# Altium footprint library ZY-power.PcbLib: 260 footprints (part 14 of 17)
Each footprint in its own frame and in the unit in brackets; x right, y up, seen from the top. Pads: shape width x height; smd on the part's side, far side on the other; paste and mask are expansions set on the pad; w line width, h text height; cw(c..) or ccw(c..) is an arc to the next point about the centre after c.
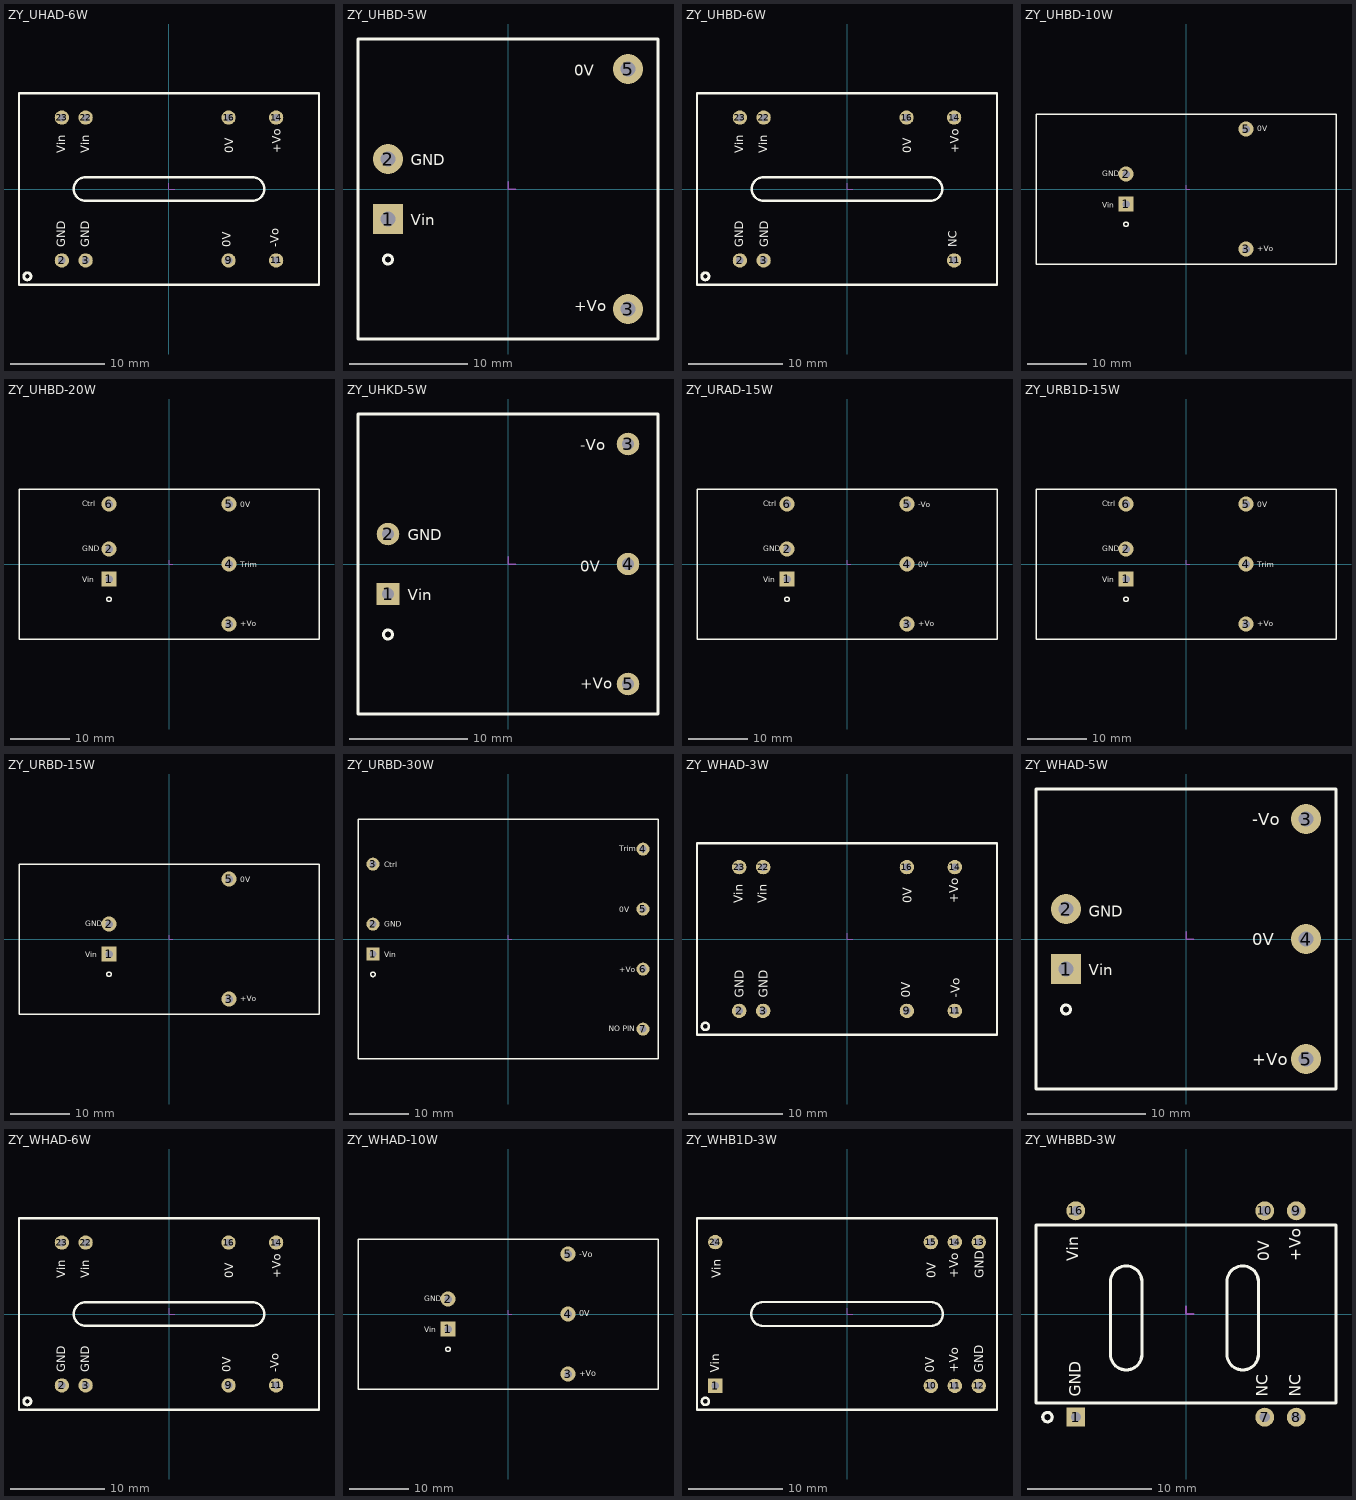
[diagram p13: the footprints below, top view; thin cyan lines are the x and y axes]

## ZY_UHAD-6W [mil]
height 413.39
pads (8):
  round 60 hole 32: 2(-450,-300) 3(-350,-300) 9(250,-300) 11(450,-300) 14(450,300) 16(250,300) 22(-350,300) 23(-450,300)
Top Overlay:
  circle w12: c-594.92,-366.57 r15
  lines w10: -629.92,-401.57 -629.92,401.57 629.92,401.57 629.92,-401.57 -629.92,-401.57 ; -400,0 ccw(c-350,0) -350,-50 350,-50 ccw(c350,0) 400,0 ccw(c350,0) 350,50 -350,50 ccw(c-350,0) -400,0
  text "0V" at 260,-245 h36
  text "GND" at -435,-245 h36
  text "GND" at -335,-245 h36
  text "Vin" at -435,150 h36
  text "Vin" at -335,150 h36
  text "-Vo" at 460,-245 h36
  text "+Vo" at 470,150 h36
  text "0V" at 270,150 h36
Mechanical 15:
  lines w5: 0,25 0,0 25,0

## ZY_UHBD-5W [mil]
height 460.63
pads (4):
  rect 100x100 hole 50: 1(-400,-100)
  round 100 hole 50: 2(-400,100) 3(400,-400) 5(400,400)
Top Overlay:
  circle w10: c-400,-235 r15
  lines w10: -500,-500 -500,500 500,500 500,-500 -500,-500
  text "GND" at -325,80 h36
  text "Vin" at -325,-120 h36
  text "+Vo" at 220,-408 h36
  text "0V" at 220,377 h36
Mechanical 15:
  lines w5: 0,25 0,0 25,0

## ZY_UHBD-6W [mil]
height 413.39
pads (7):
  round 60 hole 32: 2(-450,-300) 3(-350,-300) 11(450,-300) 14(450,300) 16(250,300) 22(-350,300) 23(-450,300)
Top Overlay:
  circle w12: c-594.92,-366.57 r15
  lines w10: -629.92,-401.57 -629.92,401.57 629.92,401.57 629.92,-401.57 -629.92,-401.57 ; -400,0 ccw(c-350,0) -350,-50 350,-50 ccw(c350,0) 400,0 ccw(c350,0) 350,50 -350,50 ccw(c-350,0) -400,0
  text "GND" at -435,-245 h36
  text "GND" at -330,-245 h36
  text "Vin" at -435,150 h36
  text "Vin" at -335,150 h36
  text "NC" at 460,-245 h36
  text "+Vo" at 470,150 h36
  text "0V" at 270,150 h36
Mechanical 15:
  lines w5: 0,25 0,0 25,0

## ZY_UHBD-10W [mil]
height 500
pads (4):
  rect 100x100 hole 50: 1(-400,-100)
  round 100 hole 50: 2(-400,100) 3(400,-400) 5(400,400)
Top Overlay:
  circle w10: c-400,-235 r15
  lines w10: -1000,-500 1000,-500 1000,500 -1000,500 -1000,-500
  text "0V" at 475,385 h36
  text "+Vo" at 475,-415 h36
  text "GND" at -560,85 h36
  text "Vin" at -560,-125 h36
Mechanical 15:
  lines w5: 0,25 0,0 25,0

## ZY_UHBD-20W [mil]
pads (6):
  rect 100x100 hole 50: 1(-400,-100)
  round 100 hole 50: 2(-400,100) 3(400,-400) 4(400,0) 5(400,400) 6(-400,400)
Top Overlay:
  circle w10: c-400,-235 r15
  lines w10: -1000,-500 -1000,500 1000,500 1000,-500 -1000,-500
  text "+Vo" at 475,-415 h36
  text "0V" at 475,380 h36
  text "GND" at -580,85 h36
  text "Vin" at -580,-120 h36
  text "Trim" at 475,-20 h36
  text "Ctrl" at -580,385 h36
Mechanical 15:
  lines w5: 0,25 0,0 25,0

## ZY_UHKD-5W [mil]
pads (5):
  rect 75x75 hole 40: 1(-400,-100)
  round 75 hole 40: 2(-400,100) 3(400,400) 4(400,0) 5(400,-400)
Top Overlay:
  circle w10: c-400,-235 r15
  lines w10: -500,-500 500,-500 500,500 -500,500 -500,-500
  text "+Vo" at 240,-415 h36
  text "-Vo" at 240,380 h36
  text "0V" at 240,-25 h36
  text "GND" at -335,80 h36
  text "Vin" at -335,-120 h36
Mechanical 15:
  lines w5: 0,25 0,0 25,0

## ZY_URAD-15W [mil]
pads (6):
  rect 100x100 hole 50: 1(-400,-100)
  round 100 hole 50: 2(-400,100) 3(400,-400) 4(400,0) 5(400,400) 6(-400,400)
Top Overlay:
  circle w10: c-400,-235 r15
  lines w10: -1000,-500 -1000,500 1000,500 1000,-500 -1000,-500
  text "+Vo" at 475,-415 h36
  text "-Vo" at 475,380 h36
  text "GND" at -560,85 h36
  text "Vin" at -560,-120 h36
  text "0V" at 475,-20 h36
  text "Ctrl" at -560,385 h36
Mechanical 15:
  lines w5: 0,25 0,0 25,0

## ZY_URB1D-15W [mil]
pads (6):
  rect 100x100 hole 50: 1(-400,-100)
  round 100 hole 50: 2(-400,100) 3(400,-400) 4(400,0) 5(400,400) 6(-400,400)
Top Overlay:
  circle w10: c-400,-235 r15
  lines w10: -1000,-500 1000,-500 1000,500 -1000,500 -1000,-500
  text "Ctrl" at -560,385 h36
  text "Trim" at 475,-20 h36
  text "Vin" at -560,-120 h36
  text "GND" at -560,85 h36
  text "0V" at 475,380 h36
  text "+Vo" at 475,-415 h36
Mechanical 15:
  lines w5: 0,25 0,0 25,0

## ZY_URBD-15W [mil]
pads (4):
  rect 100x100 hole 50: 1(-400,-100)
  round 100 hole 50: 2(-400,100) 3(400,-400) 5(400,400)
Top Overlay:
  circle w10: c-400,-235 r15
  lines w10: -1000,-500 1000,-500 1000,500 -1000,500 -1000,-500
  text "Vin" at -560,-120 h36
  text "GND" at -560,85 h36
  text "0V" at 475,380 h36
  text "+Vo" at 475,-415 h36
Mechanical 15:
  lines w5: 0,25 0,0 25,0

## ZY_URBD-30W [mil]
height 492.13
pads (7):
  rect 87x87 hole 47: 1(-900,-100)
  round 87 hole 47: 2(-900,100) 3(-900,500) 4(900,600) 5(900,200) 6(900,-200) 7(900,-600)
Top Overlay:
  circle w10: c-900,-235 r15
  lines w10: -1000,-798.43 1000,-798.43 1000,800 -1000,800 -1000,-798.43
  text "Vin" at -825,-119.21 h36
  text "+Vo" at 740,-219.21 h36
  text "0V" at 740,180.79 h36
  text "Ctrl" at -825,480.79 h36
  text "Trim" at 740,585.79 h36
  text "GND" at -825,80.79 h36
  text "NO PIN" at 670,-615 h36
Mechanical 15:
  lines w5: 0,25 0,0 25,0

## ZY_WHAD-3W [mil] "宽压输入隔离稳压双输出电源模块"
height 374.02
pads (8):
  round 60 hole 32: 2(-450,-300) 3(-350,-300) 9(250,-300) 11(450,-300) 14(450,300) 16(250,300) 22(-350,300) 23(-450,300)
Top Overlay:
  circle w10: c-590.98,-364.61 r15
  lines w10: -625.98,-399.61 -551.38,-399.61 -550,-399.61 625.98,-399.61 625.98,399.61 -625.98,399.61 -625.98,-399.61
  text "GND" at -430,-245 h36
  text "GND" at -330,-245 h36
  text "0V" at 265,-245 h36
  text "-Vo" at 470,-245 h36
  text "+Vo" at 465,150 h36
  text "0V" at 270,150 h36
  text "Vin" at -335,150 h36
  text "Vin" at -435,150 h36
Mechanical 15:
  lines w5: 0,25 0,0 25,0

## ZY_WHAD-5W [mil]
height 460.63
pads (5):
  rect 100x100 hole 50: 1(-400,-100)
  round 100 hole 50: 2(-400,100) 3(400,400) 4(400,0) 5(400,-400)
Top Overlay:
  circle w10: c-400,-235 r15
  lines w10: -500,-500 500,-500 500,500 -500,500 -500,-500
  text "-Vo" at 220,380 h40
  text "+Vo" at 220,-420 h40
  text "Vin" at -325,-120 h36
  text "GND" at -325,75 h36
  text "0V" at 220,-20 h40
Mechanical 15:
  lines w5: 0,25 0,0 25,0

## ZY_WHAD-6W [mil]
height 413.39
pads (8):
  round 60 hole 32: 2(-450,-300) 3(-350,-300) 9(250,-300) 11(450,-300) 14(450,300) 16(250,300) 22(-350,300) 23(-450,300)
Top Overlay:
  circle w12: c-594.92,-366.57 r15
  lines w10: -629.92,-401.57 629.92,-401.57 629.92,401.57 -629.92,401.57 -629.92,-401.57 ; -400,0 cw(c-350,0) -350,50 350,50 cw(c350,0) 400,0 cw(c350,0) 350,-50 -350,-50 cw(c-350,0) -400,0
  text "0V" at 270,150 h36
  text "+Vo" at 470,150 h36
  text "-Vo" at 460,-245 h36
  text "Vin" at -335,150 h36
  text "Vin" at -435,150 h36
  text "GND" at -335,-245 h36
  text "GND" at -435,-245 h36
  text "0V" at 260,-245 h36
Mechanical 15:
  lines w5: 0,25 0,0 25,0

## ZY_WHAD-10W [mil]
pads (5):
  rect 100x100 hole 50: 1(-400,-100)
  round 100 hole 50: 2(-400,100) 3(400,-400) 4(400,0) 5(400,400)
Top Overlay:
  circle w10: c-400,-235 r15
  lines w10: -1000,-500 1000,-500 1000,500 -1000,500 -1000,-500
  text "Vin" at -560,-120 h36
  text "GND" at -560,85 h36
  text "0V" at 475,-15 h40
  text "+Vo" at 475,-415 h40
  text "-Vo" at 475,380 h40
Mechanical 15:
  lines w5: 0,25 0,0 25,0

## ZY_WHB1D-3W [mil]
height 413.39
pads (8):
  rect 60x60 hole 32: 1(-550,-300)
  round 60 hole 32: 10(350,-300) 11(450,-300) 12(550,-300) 13(550,300) 14(450,300) 15(350,300) 24(-550,300)
Top Overlay:
  circle w10: c-590.98,-364.61 r15
  lines w10: -550,-399.61 -551.38,-399.61 ; -551.38,-399.61 625.98,-399.61 625.98,399.61 -625.98,399.61 -625.98,-399.61 -551.38,-399.61 ; -400,0 ccw(c-350,0) -350,-50 350,-50 ccw(c350,0) 400,0 ccw(c350,0) 350,50 -350,50 ccw(c-350,0) -400,0
  text "GND" at 571,150 h36
  text "+Vo" at 465,150 h36
  text "0V" at 371,150 h36
  text "+Vo" at 465,-245 h36
  text "0V" at 364,-245 h36
  text "Vin" at -534,-245 h36
  text "Vin" at -526,150 h36
  text "GND" at 568,-245 h36
Mechanical 15:
  lines w5: 0,25 0,0 25,0

## ZY_WHBBD-3W [mil]
height 181.1
pads (6):
  rect 60x60 hole 32: 1(-350,-327.56)
  round 60 hole 32: 7(250,-327.56) 8(350,-327.56) 9(350,327.56) 10(250,327.56) 16(-350,327.56)
Top Overlay:
  circle w10: c-440,-327.56 r15
  lines w9.65: -476.38,-282.48 -476.38,282.48 ; 476.38,-282.48 476.38,282.48
  lines w10: -476.38,-282.48 476.38,-282.48 ; -476.38,282.48 476.38,282.48 ; -240,-127.56 ccw(c-190,-127.56) -190,-177.56 ccw(c-190,-127.56) -140,-127.56 -140,102.44 ccw(c-190,102.44) -190,152.44 ccw(c-190,102.44) -240,102.44 -240,-127.56 ; 130,-127.56 ccw(c180,-127.56) 180,-177.56 ccw(c180,-127.56) 230,-127.56 230,102.44 ccw(c180,102.44) 180,152.44 ccw(c180,102.44) 130,102.44 130,-127.56
  text "NC" at 260,-262.56 h36
  text "+Vo" at 365,167.56 h36
  text "0V" at 265,167.56 h36
  text "Vin" at -342,167.56 h36
  text "GND" at -335,-262.56 h36
  text "NC" at 365,-262.56 h36
Mechanical 15:
  lines w5: 0,25 0,0 25,0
